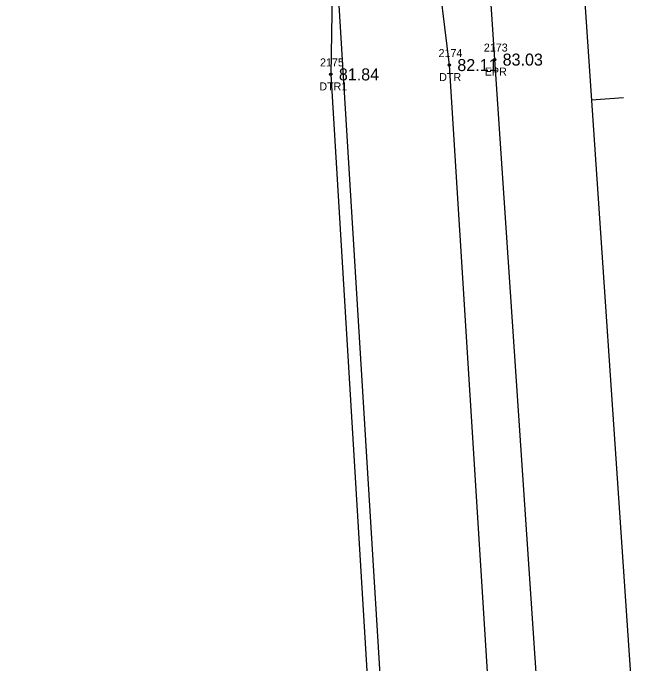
# Model space of a CAD drawing. Extents: x 2139392 to 2143384, y 505395 to 510520.
# Drawn here: x 2140521 to 2140601.5, y 507254.6 to 507335.9 of the extents above; entities that cross this region are included whole.
import ezdxf

# ---------------------------------------------------------------- set-up
doc = ezdxf.new("R2010")
doc.units = 0
for name, color, linetype in [('RD_EX_H2O', 7, 'Continuous'), ('RD_EX_H2O_txCode', 7, 'Continuous'), ('RD_EX_Road', 7, 'Continuous'), ('RD_EX_Road_txCode', 7, 'Continuous'), ('RD_EX_TX_H2O_ELEV', 7, 'Continuous'), ('RD_EX_TX_Road_ELEV', 7, 'Continuous'), ('RD_EX_VEG', 7, 'Continuous'), ('RD_HC_Cl', 7, 'Continuous'), ('RD_HC_Data_Tic', 7, 'Continuous'), ('RD_SMD_Locator', 7, 'Continuous')]:
    doc.layers.add(name, color=color, linetype=linetype)

msp = doc.modelspace()

# ---------------------------------------------------------------- linework, layer by layer
at = {"layer": 'RD_EX_H2O'}
for points in [[(2140566.756, 507360.34), (2140561.097, 507358.979), (2140560.598, 507328.237), (2140566.882, 507224.15), (2140571.596, 507184.274)], [(2140566.756, 507360.34), (2140571.964, 507357.241), (2140575.379, 507329.403), (2140581.844, 507225.739), (2140584.452, 507186.919), (2140580.805, 507180.276), (2140573.148, 507179.276), (2140571.596, 507184.274)]]:
    msp.add_lwpolyline(points, dxfattribs=at)
at = {"layer": 'RD_EX_Road'}
msp.add_lwpolyline([(2140559.738, 507699.593), (2140559.812, 507681.925), (2140560.304, 507666.177), (2140562.281, 507610.801), (2140566.398, 507547.539), (2140570.03, 507492.805), (2140573.817, 507437.377), (2140577.821, 507379.035), (2140579.377, 507354.439), (2140581.03, 507330.086), (2140587.991, 507226.365), (2140590.862, 507184.676), (2140593.073, 507153.161), (2140595.225, 507123.785), (2140602.702, 507012.785), (2140610.007, 506906.422), (2140617.095, 506803.242), (2140624.734, 506690.174), (2140631.756, 506586.092), (2140639.513, 506472.795), (2140646.099, 506374.383), (2140653.644, 506264.114)], dxfattribs=at)
at = {"layer": 'RD_EX_VEG'}
msp.add_lwpolyline([(2140406.687, 507704.714), (2140540.941, 507674.412), (2140569.48, 507207.834), (2140538.654, 507191.927)], dxfattribs=at)
at = {"layer": 'RD_HC_Cl'}
msp.add_line((2140574.741, 507595.124), (2140664.078, 506281.809), dxfattribs=at)
at = {"layer": 'RD_HC_Data_Tic'}
msp.add_line((2140593.111, 507325.075), (2140597.101, 507325.346), dxfattribs=at)
at = {"layer": 'RD_SMD_Locator'}
for centre in [(2140581.03, 507330.086), (2140575.379, 507329.403), (2140560.598, 507328.237)]:
    msp.add_circle(centre, 0.15, dxfattribs=at)

# ---------------------------------------------------------------- texts
at = {"layer": 'RD_EX_H2O_txCode'}
for s, p in [('2174', (2140574.033, 507330.403)), ('2175', (2140559.251, 507329.237)), ('DTR', (2140574.112, 507327.403)), ('DTR1', (2140559.165, 507326.237))]:
    msp.add_text(s, height=1, dxfattribs=at).set_placement(p)
at = {"layer": 'RD_EX_Road_txCode'}
for s, p in [('2173', (2140579.684, 507331.086)), ('EPR', (2140579.802, 507328.086))]:
    msp.add_text(s, height=1, dxfattribs=at).set_placement(p)
at = {"layer": 'RD_EX_TX_H2O_ELEV'}
for s, p in [('82.11', (2140576.379, 507328.653)), ('81.84', (2140561.598, 507327.487))]:
    msp.add_text(s, height=1.5, dxfattribs=at).set_placement(p)
at = {"layer": 'RD_EX_TX_Road_ELEV'}
msp.add_text('83.03', height=1.5, dxfattribs=at).set_placement((2140582.03, 507329.336))

doc.saveas('drawing.dxf')
